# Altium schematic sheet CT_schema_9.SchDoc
size 297 x 239 mm
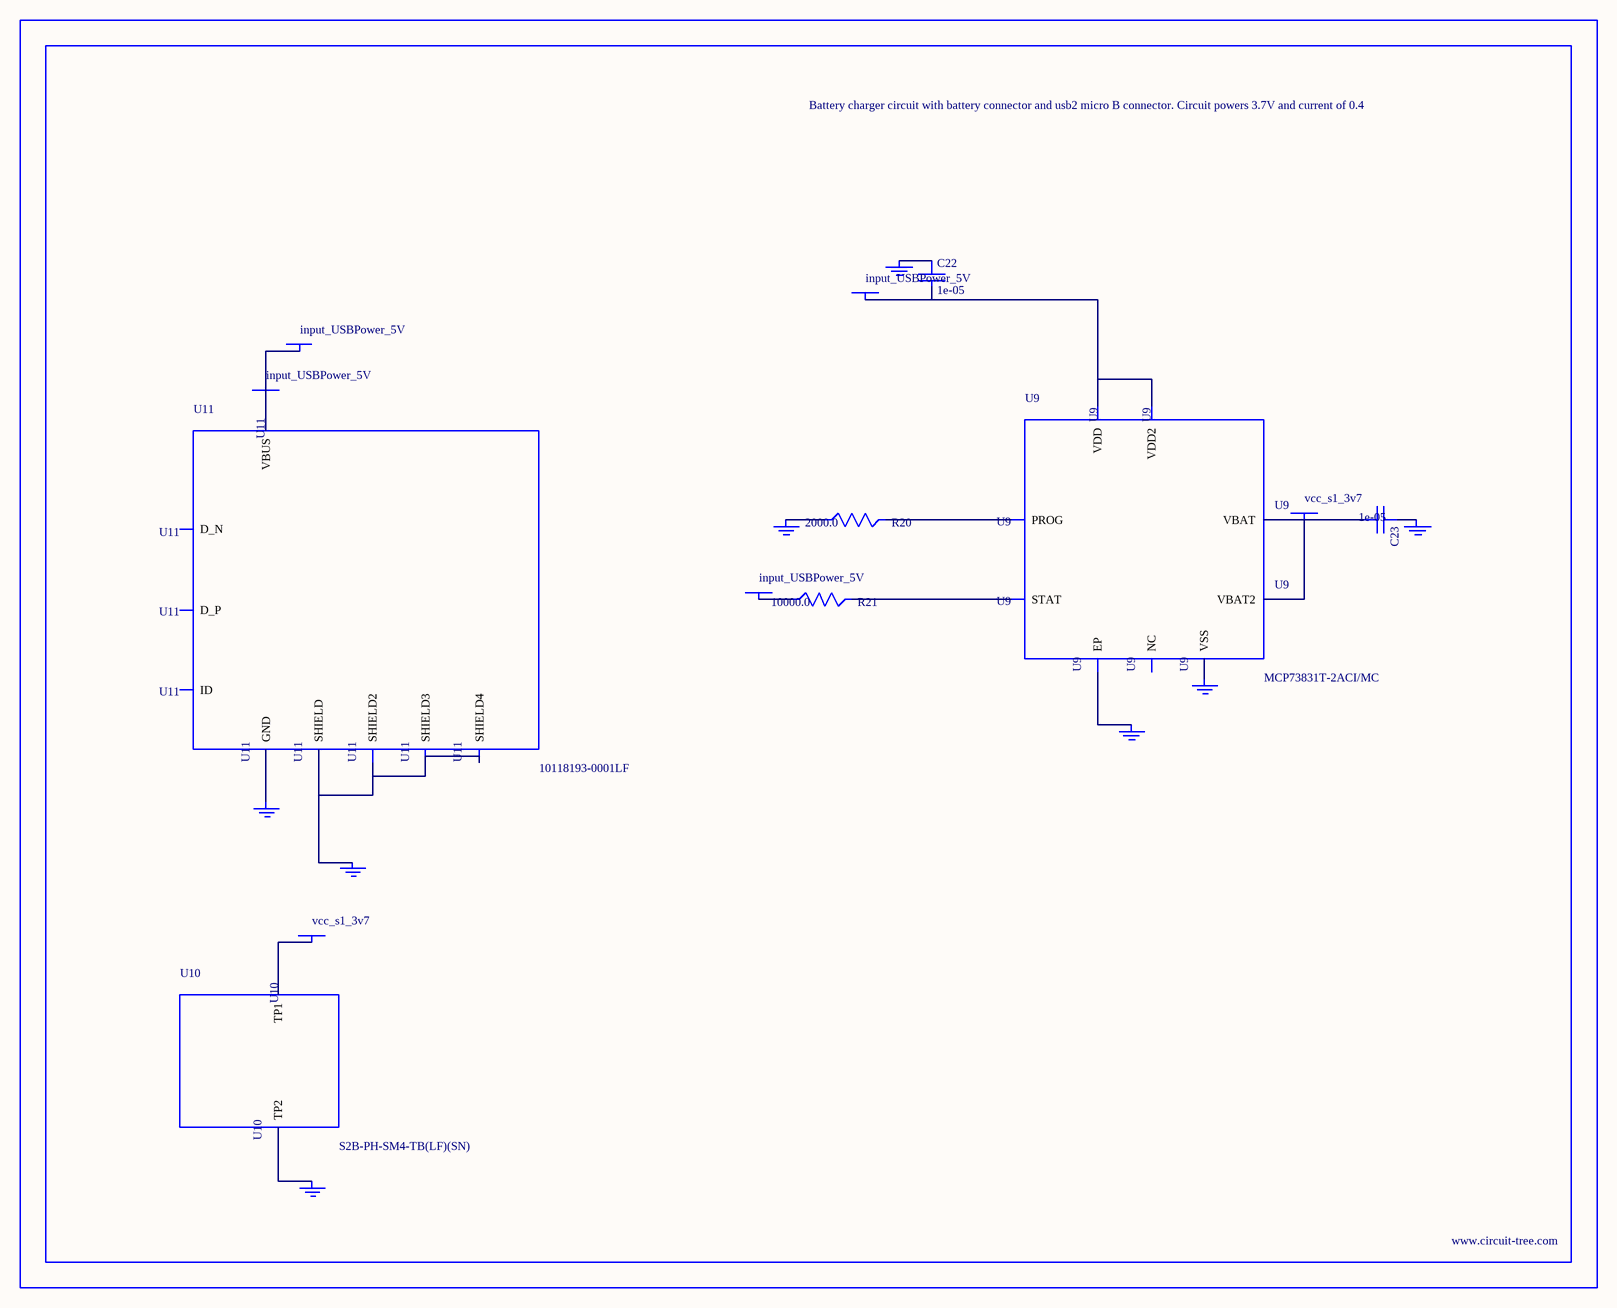
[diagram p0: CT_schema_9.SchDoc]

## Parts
BORDER8  (no value)
C22  1e-05  [C1206]
C23  1e-05  [C1206]
GND_INSTANCE_8_0  (no value)
GND_INSTANCE_8_1  (no value)
GND_INSTANCE_8_2  (no value)
GND_INSTANCE_8_3  (no value)
GND_INSTANCE_8_4  (no value)
GND_INSTANCE_8_5  (no value)
GND_INSTANCE_8_6  (no value)
GND_INSTANCE_8_7  (no value)
POWER_INSTANCE_8_0  input_USBPower_5V
POWER_INSTANCE_8_1  input_USBPower_5V
POWER_INSTANCE_8_2  vcc_s1_3v7
POWER_INSTANCE_8_3  vcc_s1_3v7
POWER_INSTANCE_8_4  input_USBPower_5V
POWER_INSTANCE_8_5  input_USBPower_5V
R20  2000.0  [R0603]
R21  10000.0  [R0603]
U9  MCP73831T-2ACI/MC  [DFN8_2X3MC]
U10  S2B-PH-SM4-TB(LF)(SN)  [JST-2-SMD]
U11  10118193-0001LF  [FCI_10118193-0001LF]

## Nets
NetC22_1: C22.1 GND_INSTANCE_8_0.0(GND)
NetC22_2: C22.2 POWER_INSTANCE_8_0.0(PWR) U9.1(VDD) U9.2(VDD2)
NetC23_1: C23.1 GND_INSTANCE_8_1.0(GND)
NetC23_2: C23.2 POWER_INSTANCE_8_2.0(PWR) U9.3(VBAT) U9.4(VBAT2)
NetGND_INSTANCE_8_2_0: GND_INSTANCE_8_2.0(GND) R20.1
NetGND_INSTANCE_8_3_0: GND_INSTANCE_8_3.0(GND) U9.9(EP)
NetGND_INSTANCE_8_4_0: GND_INSTANCE_8_4.0(GND) U9.6(VSS)
NetGND_INSTANCE_8_5_0: GND_INSTANCE_8_5.0(GND) U10.2(TP2)
NetGND_INSTANCE_8_6_0: GND_INSTANCE_8_6.0(GND) U11.6(SHIELD) U11.7(SHIELD2) U11.8(SHIELD3) U11.9(SHIELD4)
NetGND_INSTANCE_8_7_0: GND_INSTANCE_8_7.0(GND) U11.5(GND)
NetPOWER_INSTANCE_8_1_0: POWER_INSTANCE_8_1.0(PWR) R21.1
NetPOWER_INSTANCE_8_3_0: POWER_INSTANCE_8_3.0(PWR) U10.1(TP1)
NetPOWER_INSTANCE_8_4_0: POWER_INSTANCE_8_4.0(PWR) POWER_INSTANCE_8_5.0(PWR) U11.1(VBUS)
NetR20_2: R20.2 U9.8(PROG)
NetR21_2: R21.2 U9.5(STAT)

Not connected (* = marked no-connect by the designer): U9 7(NC); U11 2(D_N) 3(D_P) 4(ID)

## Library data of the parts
BORDER8 = BORDER_PAGE8
C22 C23 = C1206C106K3RACTU
GND_INSTANCE_8_0-GND_INSTANCE_8_7 = GND
POWER_INSTANCE_8_0-POWER_INSTANCE_8_5 = PWR
R20 = RC0603JR-072KL
R21 = RC0603JR-0710KL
